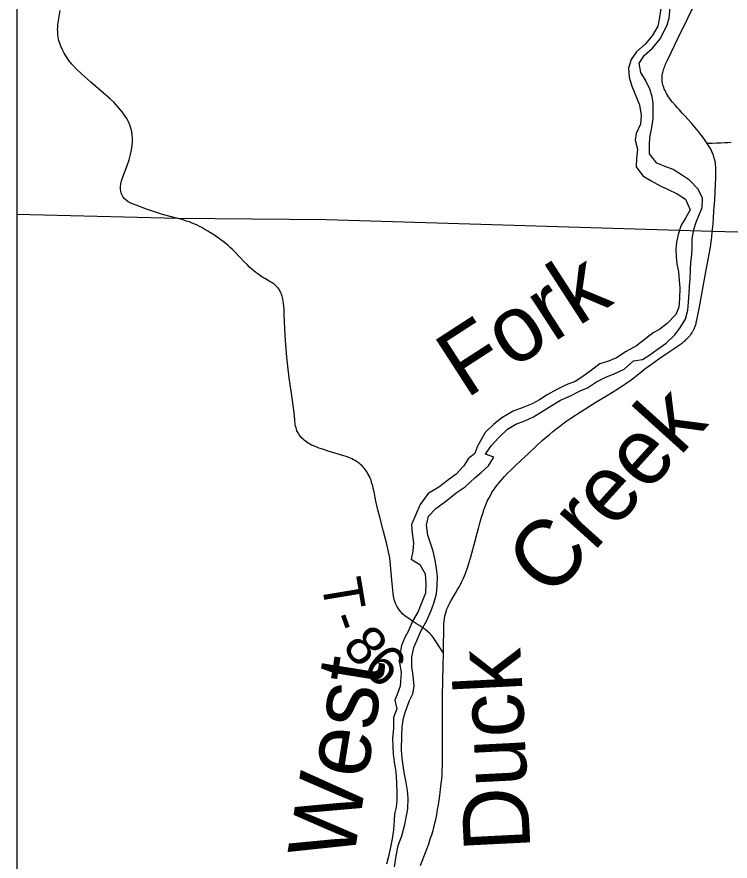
# Model space of a CAD drawing. Extents: x -10.5 to 40.6, y -3.2 to 22.
# Drawn here: x -10.544 to -9.528, y 15.152 to 16.355 of the extents above; entities that cross this region are included whole.
import ezdxf

# ---------------------------------------------------------------- set-up
doc = ezdxf.new("R2010")
doc.units = 0
for name, color, linetype in [('GM_X_Major_River', 7, 'Continuous'), ('GM_X_Major_River_Text', 7, 'Continuous'), ('GM_X_State_Route', 7, 'Continuous'), ('GM_X_Township_Road', 7, 'Continuous'), ('GM_X_Township_Road_Text', 7, 'Continuous'), ('GM_X_Township_Text', 7, 'Continuous'), ('SH_Text', 7, 'Continuous')]:
    doc.layers.add(name, color=color, linetype=linetype)

msp = doc.modelspace()

# ---------------------------------------------------------------- linework, layer by layer
at = {"layer": 'GM_X_Major_River'}
for points in [[(-9.8767, 15.7321), (-9.8682, 15.7436), (-9.8573, 15.7555), (-9.845, 15.7674), (-9.8333, 15.7748), (-9.8205, 15.7795), (-9.8081, 15.7854), (-9.7945, 15.7935), (-9.7829, 15.8009), (-9.7694, 15.809), (-9.7554, 15.8153), (-9.7415, 15.8223), (-9.7309, 15.8266), (-9.7181, 15.8352), (-9.7038, 15.8422), (-9.6933, 15.8465), (-9.679, 15.8531), (-9.6655, 15.8651), (-9.6526, 15.8671), (-9.6421, 15.8734), (-9.6316, 15.8811), (-9.6188, 15.89), (-9.6065, 15.9019), (-9.5994, 15.9115), (-9.5916, 15.9245), (-9.588, 15.9371), (-9.587, 15.9488), (-9.5864, 15.9617), (-9.5858, 15.9716), (-9.5848, 15.9815), (-9.5842, 15.9951), (-9.5836, 16.005), (-9.5826, 16.016), (-9.582, 16.0263), (-9.5821, 16.0388), (-9.5797, 16.0525), (-9.576, 16.0628), (-9.572, 16.0731), (-9.5676, 16.0838), (-9.5674, 16.097), (-9.5733, 16.1098), (-9.5859, 16.1226), (-9.597, 16.1304), (-9.6089, 16.1378), (-9.6203, 16.1422), (-9.6325, 16.147), (-9.6426, 16.1601), (-9.6427, 16.1726), (-9.6421, 16.1836), (-9.6393, 16.1977), (-9.6376, 16.2106), (-9.6373, 16.2205), (-9.6375, 16.2319), (-9.6391, 16.2421), (-9.6423, 16.2523), (-9.6482, 16.2651), (-9.6551, 16.276), (-9.6576, 16.2896), (-9.6498, 16.3011), (-9.6385, 16.3107), (-9.6273, 16.3242), (-9.6181, 16.3429), (-9.6149, 16.3535), (-9.6129, 16.3741)], [(-9.6268, 16.3678), (-9.6285, 16.3545), (-9.631, 16.3423), (-9.6388, 16.3282), (-9.6489, 16.3167), (-9.6612, 16.3055), (-9.6687, 16.2948), (-9.6727, 16.2822), (-9.6717, 16.2693), (-9.6681, 16.2565), (-9.6572, 16.2301), (-9.6547, 16.2153), (-9.6556, 16.2024), (-9.6619, 16.1894), (-9.6633, 16.1799), (-9.6597, 16.1667), (-9.6614, 16.1542), (-9.6616, 16.1416), (-9.652, 16.1289), (-9.6405, 16.1218), (-9.6264, 16.1141), (-9.6169, 16.11), (-9.6035, 16.103), (-9.5913, 16.0956), (-9.5846, 16.0805), (-9.5913, 16.0683), (-9.5976, 16.0587), (-9.6019, 16.045), (-9.6041, 16.0343), (-9.6051, 16.0244), (-9.6049, 16.0135), (-9.6037, 16.0032), (-9.6016, 15.9919), (-9.6003, 15.9794), (-9.5994, 15.9691), (-9.6, 15.954), (-9.6009, 15.9414), (-9.6053, 15.9311), (-9.6177, 15.9181), (-9.6278, 15.91), (-9.6376, 15.9049), (-9.6481, 15.8968), (-9.6612, 15.8864), (-9.6759, 15.8782), (-9.6898, 15.8693), (-9.7011, 15.8646), (-9.7136, 15.8606), (-9.7252, 15.8517), (-9.7376, 15.8425), (-9.7489, 15.8355), (-9.7617, 15.8308), (-9.7749, 15.8241), (-9.7888, 15.8164), (-9.7993, 15.8094), (-9.8098, 15.8036), (-9.8242, 15.7981), (-9.837, 15.7933), (-9.8532, 15.7836), (-9.8648, 15.7747), (-9.8772, 15.7628), (-9.8883, 15.7422), (-9.8915, 15.7327)], [(-9.8915, 15.7327), (-9.9013, 15.7253), (-9.9076, 15.7154), (-9.9181, 15.7035), (-9.9305, 15.6946), (-9.9432, 15.6849), (-9.9583, 15.676), (-9.9698, 15.6603), (-9.9819, 15.6317), (-9.981, 15.6195), (-9.9793, 15.6055), (-9.9799, 15.5938), (-9.9824, 15.582), (-9.9702, 15.5745), (-9.9624, 15.5614), (-9.9614, 15.547), (-9.962, 15.5337), (-9.9671, 15.5207), (-9.9727, 15.5074), (-9.9804, 15.4936), (-9.9863, 15.4802), (-9.9915, 15.4703), (-9.9963, 15.4589), (-9.9984, 15.4456), (-9.999, 15.4346), (-9.9969, 15.4209), (-9.9981, 15.4012), (-10.0018, 15.3909), (-10.0058, 15.381), (-10.003, 15.3689), (-10.0078, 15.3563), (-10.0076, 15.3411), (-10.0089, 15.3267), (-10.0084, 15.3161), (-10.0082, 15.3043), (-10.0065, 15.2929), (-10.0049, 15.2823), (-10.004, 15.2729), (-10.0035, 15.2626), (-10.0029, 15.2494), (-10.0031, 15.238), (-10.0038, 15.2285), (-10.0063, 15.219), (-10.0069, 15.2095), (-10.0075, 15.1962), (-10.0096, 15.1836), (-10.0114, 15.1741), (-10.0142, 15.1604), (-10.0175, 15.1475)], [(-10.006, 15.1435), (-10.004, 15.1591), (-10.0011, 15.1739), (-9.996, 15.1876), (-9.9913, 15.204), (-9.9892, 15.2162), (-9.9874, 15.2261), (-9.9869, 15.2416), (-9.9878, 15.2522), (-9.9898, 15.264), (-9.9923, 15.278), (-9.994, 15.2878), (-9.9952, 15.298), (-9.9961, 15.3102), (-9.9957, 15.3307), (-9.9955, 15.3432), (-9.9933, 15.3553), (-9.9904, 15.3649), (-9.9846, 15.3809), (-9.9802, 15.3904), (-9.9784, 15.4011), (-9.9794, 15.4158), (-9.9814, 15.4287), (-9.9816, 15.4428), (-9.9788, 15.4564), (-9.9725, 15.4706), (-9.9681, 15.4805), (-9.9603, 15.4946), (-9.9541, 15.5088), (-9.9501, 15.5194), (-9.9465, 15.5328), (-9.9455, 15.5449), (-9.9449, 15.5574), (-9.9462, 15.5688), (-9.9482, 15.5809), (-9.9511, 15.5934), (-9.9546, 15.6036), (-9.9586, 15.6164), (-9.9607, 15.6308), (-9.9578, 15.6434), (-9.9473, 15.6545), (-9.9335, 15.6646), (-9.9181, 15.6769), (-9.9053, 15.6854), (-9.8918, 15.6981), (-9.8821, 15.7062), (-9.872, 15.7151), (-9.8646, 15.7277), (-9.8767, 15.7321)]]:
    msp.add_lwpolyline(points, dxfattribs=at)
at = {"layer": 'GM_X_State_Route'}
for points in [[(-9.5532, 16.0492), (-9.5525, 16.056), (-9.5517, 16.0675), (-9.5508, 16.0793), (-9.5502, 16.088), (-9.5497, 16.0955), (-9.5493, 16.1028), (-9.5491, 16.1084), (-9.5488, 16.1135), (-9.5486, 16.1178), (-9.5483, 16.1241), (-9.5482, 16.1303), (-9.5481, 16.1341), (-9.5482, 16.1373), (-9.5483, 16.1417), (-9.5485, 16.1443), (-9.5488, 16.1473), (-9.5493, 16.1499), (-9.5499, 16.1526), (-9.5505, 16.1547), (-9.5509, 16.1561), (-9.5515, 16.1578), (-9.5521, 16.1594), (-9.5526, 16.1608), (-9.5533, 16.1622), (-9.5538, 16.1635), (-9.5545, 16.165), (-9.5552, 16.1664), (-9.5558, 16.1676), (-9.5568, 16.1693), (-9.558, 16.1713), (-9.5603, 16.175), (-9.5633, 16.1794), (-9.5664, 16.1837), (-9.5699, 16.1884), (-9.573, 16.1921), (-9.5781, 16.1982), (-9.583, 16.2039), (-9.588, 16.2095), (-9.592, 16.214), (-9.596, 16.2184), (-9.6001, 16.2228), (-9.6032, 16.2263), (-9.6055, 16.2289), (-9.6097, 16.2338), (-9.6121, 16.2368), (-9.6142, 16.2395), (-9.6157, 16.2415), (-9.6171, 16.2438), (-9.6183, 16.246), (-9.6195, 16.2483), (-9.6206, 16.2505), (-9.6216, 16.2527), (-9.6224, 16.2547), (-9.6232, 16.257), (-9.6238, 16.2591), (-9.6243, 16.2609), (-9.6246, 16.2627), (-9.6248, 16.2648), (-9.6249, 16.2667), (-9.6249, 16.2685), (-9.6247, 16.2704), (-9.6245, 16.2727), (-9.6241, 16.2745), (-9.6238, 16.2762), (-9.6233, 16.2781), (-9.6226, 16.2803), (-9.6219, 16.2825), (-9.6212, 16.2844), (-9.6205, 16.2861), (-9.6198, 16.2878), (-9.6171, 16.2938), (-9.6115, 16.3055), (-9.6021, 16.3245), (-9.5881, 16.3535), (-9.5738, 16.3832)], [(-9.9691, 15.1455), (-9.9657, 15.1541), (-9.9628, 15.1618), (-9.9602, 15.1687), (-9.9574, 15.1765), (-9.9557, 15.1814), (-9.9544, 15.1856), (-9.9531, 15.1894), (-9.9521, 15.1927), (-9.9513, 15.1954), (-9.9506, 15.1982), (-9.9498, 15.2013), (-9.9486, 15.206), (-9.9475, 15.2109), (-9.9461, 15.2177), (-9.9447, 15.2255), (-9.9437, 15.2318), (-9.9422, 15.2416), (-9.9405, 15.254), (-9.9396, 15.2622), (-9.9389, 15.2686), (-9.9384, 15.2747), (-9.9381, 15.2808), (-9.9378, 15.2876), (-9.9378, 15.2939), (-9.9379, 15.2993), (-9.9379, 15.3099), (-9.9378, 15.3255), (-9.9378, 15.336), (-9.9377, 15.3633), (-9.9377, 15.3869), (-9.9367, 15.4311), (-9.9363, 15.4483), (-9.9362, 15.4607), (-9.9361, 15.4793), (-9.9361, 15.4844), (-9.9358, 15.489), (-9.9355, 15.4935), (-9.9349, 15.4977), (-9.9343, 15.501), (-9.9335, 15.5043), (-9.9326, 15.5074), (-9.9315, 15.5107), (-9.9304, 15.5138), (-9.929, 15.517), (-9.9273, 15.5201), (-9.9255, 15.5234), (-9.9194, 15.5336), (-9.9164, 15.5388), (-9.9137, 15.5432), (-9.9122, 15.5462), (-9.9105, 15.5493), (-9.9092, 15.5521), (-9.9079, 15.555), (-9.9065, 15.5584), (-9.9051, 15.5619), (-9.9019, 15.5714), (-9.8976, 15.5857), (-9.8914, 15.6085), (-9.8884, 15.6192), (-9.8865, 15.6258), (-9.8845, 15.6335), (-9.882, 15.6419), (-9.8805, 15.6473), (-9.8789, 15.6524), (-9.8775, 15.6562), (-9.8762, 15.6597), (-9.8752, 15.6622), (-9.8741, 15.6647), (-9.8729, 15.6672), (-9.8715, 15.6697), (-9.8696, 15.673), (-9.8673, 15.6771), (-9.8649, 15.6808), (-9.8628, 15.684), (-9.8604, 15.6873), (-9.8582, 15.6899), (-9.8553, 15.6933), (-9.8526, 15.6965), (-9.8496, 15.6999), (-9.8454, 15.7044), (-9.8404, 15.7092), (-9.8336, 15.7157), (-9.8265, 15.7224), (-9.8151, 15.733), (-9.8045, 15.7432), (-9.7956, 15.7512), (-9.7902, 15.756), (-9.7853, 15.7602), (-9.7808, 15.764), (-9.7762, 15.7677), (-9.7712, 15.7716), (-9.7664, 15.7752), (-9.7606, 15.7795), (-9.7547, 15.7834), (-9.7402, 15.7929), (-9.7191, 15.806), (-9.7017, 15.8167), (-9.6895, 15.8241), (-9.6843, 15.8274), (-9.6797, 15.8304), (-9.6744, 15.834), (-9.6706, 15.8367), (-9.6669, 15.8395), (-9.6579, 15.8465), (-9.6493, 15.8534), (-9.64, 15.8604), (-9.6294, 15.8681), (-9.6192, 15.8748), (-9.6076, 15.8825), (-9.6028, 15.8858), (-9.5983, 15.8888), (-9.597, 15.8898), (-9.5956, 15.8908), (-9.5942, 15.8919), (-9.5925, 15.8933), (-9.5909, 15.8948), (-9.5898, 15.8959), (-9.5888, 15.8969), (-9.5871, 15.8987), (-9.5862, 15.8996), (-9.5854, 15.9007), (-9.5846, 15.9016), (-9.5838, 15.9027), (-9.5824, 15.9047), (-9.5818, 15.9057), (-9.5812, 15.9067), (-9.5806, 15.9077), (-9.58, 15.9087), (-9.5795, 15.9097), (-9.579, 15.9107), (-9.5785, 15.9119), (-9.578, 15.9132), (-9.5775, 15.9144), (-9.5771, 15.9156), (-9.5767, 15.9167), (-9.5764, 15.918), (-9.576, 15.9195), (-9.5753, 15.923), (-9.5715, 15.9418), (-9.5641, 15.9816), (-9.5614, 15.9973), (-9.5591, 16.0094), (-9.5577, 16.0172), (-9.556, 16.0269), (-9.555, 16.0345), (-9.554, 16.0415), (-9.5532, 16.0492)]]:
    msp.add_lwpolyline(points, dxfattribs=at)
at = {"layer": 'GM_X_Township_Road'}
for points in [[(-10.3141, 16.0678), (-10.3149, 16.068), (-10.3367, 16.0738), (-10.3468, 16.0769), (-10.3597, 16.0813), (-10.3743, 16.0868), (-10.3812, 16.0895), (-10.3857, 16.0917), (-10.3887, 16.0939), (-10.3909, 16.096), (-10.3929, 16.0984), (-10.3945, 16.1011), (-10.3957, 16.1039), (-10.3965, 16.1069), (-10.3969, 16.11), (-10.3968, 16.1137), (-10.3962, 16.1174), (-10.3952, 16.1217), (-10.3923, 16.1299), (-10.3878, 16.1421), (-10.3846, 16.1515), (-10.3824, 16.1593), (-10.3809, 16.166), (-10.38, 16.1721), (-10.3796, 16.1771), (-10.3796, 16.182), (-10.38, 16.187), (-10.3808, 16.1919), (-10.382, 16.1967), (-10.3835, 16.2014), (-10.3855, 16.206), (-10.3878, 16.2104), (-10.3901, 16.2141), (-10.3945, 16.2201), (-10.4004, 16.2273), (-10.4059, 16.2332), (-10.4113, 16.2384), (-10.4212, 16.2469), (-10.4391, 16.2623), (-10.452, 16.2739), (-10.4601, 16.2816), (-10.466, 16.288), (-10.4704, 16.2933), (-10.474, 16.2983), (-10.4772, 16.3036), (-10.4797, 16.3086), (-10.4819, 16.3138), (-10.483, 16.3165), (-10.4839, 16.3191), (-10.4846, 16.3215), (-10.4852, 16.3243), (-10.4856, 16.327), (-10.486, 16.33), (-10.4862, 16.3326), (-10.4863, 16.335), (-10.4864, 16.3376), (-10.4863, 16.3405), (-10.486, 16.3439), (-10.4856, 16.3473), (-10.4828, 16.3645)], [(-9.5263, 16.1763), (-9.5305, 16.1759), (-9.5349, 16.1757), (-9.5411, 16.1754), (-9.5467, 16.1752), (-9.5533, 16.175), (-9.5603, 16.175)], [(-9.9715, 15.4879), (-9.9749, 15.4902), (-9.9822, 15.495), (-9.9858, 15.4974), (-9.9909, 15.5009), (-9.9942, 15.5037), (-9.9971, 15.5069), (-10.0005, 15.5113), (-10.0029, 15.515), (-10.0045, 15.5183), (-10.0058, 15.5218), (-10.007, 15.5266), (-10.0081, 15.5334), (-10.0097, 15.5476), (-10.0118, 15.5736), (-10.0131, 15.5841), (-10.0146, 15.5926), (-10.017, 15.6035), (-10.0218, 15.6216), (-10.0278, 15.6438), (-10.03, 15.6528), (-10.0326, 15.665), (-10.0353, 15.6783), (-10.0364, 15.683), (-10.0373, 15.6868), (-10.0383, 15.6899), (-10.0391, 15.6927), (-10.0401, 15.6957), (-10.0411, 15.6979), (-10.042, 15.7001), (-10.0431, 15.7024), (-10.044, 15.7041), (-10.0452, 15.7062), (-10.0466, 15.7082), (-10.0481, 15.7102), (-10.0495, 15.712), (-10.0514, 15.714), (-10.053, 15.7156), (-10.0549, 15.7174), (-10.0568, 15.7189), (-10.0588, 15.7205), (-10.0604, 15.7216), (-10.0624, 15.7229), (-10.0646, 15.7241), (-10.0668, 15.7253), (-10.069, 15.7264), (-10.0713, 15.7273), (-10.075, 15.7286), (-10.0784, 15.7297), (-10.101, 15.7363), (-10.1061, 15.7379), (-10.1105, 15.7394), (-10.1143, 15.7407), (-10.118, 15.7422), (-10.1215, 15.7437), (-10.1243, 15.745), (-10.1268, 15.7463), (-10.1292, 15.7477), (-10.1313, 15.7491), (-10.1333, 15.7504), (-10.1351, 15.7519), (-10.1366, 15.7532), (-10.1392, 15.7559), (-10.1415, 15.7588), (-10.1435, 15.7622), (-10.1452, 15.7653), (-10.1461, 15.7676), (-10.1466, 15.7694), (-10.1472, 15.772), (-10.1477, 15.7743), (-10.1485, 15.781), (-10.1493, 15.7909), (-10.1519, 15.8125), (-10.1533, 15.8217), (-10.1563, 15.8407), (-10.1583, 15.8574), (-10.1596, 15.8704), (-10.1616, 15.8939), (-10.1625, 15.9107), (-10.1633, 15.9311), (-10.1636, 15.9384), (-10.164, 15.9436), (-10.1643, 15.9469), (-10.1648, 15.9503), (-10.1653, 15.9529), (-10.1659, 15.9552), (-10.1665, 15.9573), (-10.1671, 15.9594), (-10.1679, 15.9616), (-10.1688, 15.9634), (-10.1696, 15.9649), (-10.1703, 15.9662), (-10.1715, 15.9681), (-10.1728, 15.9696), (-10.1747, 15.9716), (-10.1764, 15.9731), (-10.1778, 15.9743), (-10.1793, 15.9753), (-10.1808, 15.9763), (-10.1825, 15.9773), (-10.1911, 15.9823), (-10.194, 15.984), (-10.1974, 15.9863), (-10.2011, 15.9889), (-10.2039, 15.9911), (-10.2072, 15.9937), (-10.2096, 15.9959), (-10.2128, 15.9987), (-10.2164, 16.0022), (-10.2205, 16.0064), (-10.2263, 16.0125), (-10.2349, 16.0214), (-10.2378, 16.0243), (-10.2404, 16.0265), (-10.2434, 16.0293), (-10.2464, 16.0318), (-10.2506, 16.0351), (-10.2538, 16.0375), (-10.2591, 16.0412), (-10.2629, 16.044), (-10.2685, 16.0476), (-10.2723, 16.05), (-10.2764, 16.0525), (-10.2809, 16.0551), (-10.2842, 16.0568), (-10.2875, 16.0585), (-10.291, 16.0601), (-10.2944, 16.0614), (-10.2984, 16.063), (-10.3026, 16.0644), (-10.3075, 16.0659), (-10.3133, 16.0675), (-10.3141, 16.0678)], [(-9.9363, 15.4483), (-9.9507, 15.4702), (-9.9533, 15.4737), (-9.9563, 15.4769), (-9.9595, 15.4797), (-9.9646, 15.4833), (-9.9715, 15.4879)]]:
    msp.add_lwpolyline(points, dxfattribs=at)
at = {"layer": 'GM_X_Township_Text'}
msp.add_lwpolyline([(-10.5445, 19.4241), (-10.5445, 16.0741), (-10.3151, 16.0685), (-10.1031, 16.0664), (-9.5534, 16.0497), (-8.7017, 16.0275), (-8.5879, 16.0247), (-8.2615, 16.0223), (-8.2451, 17.3912), (-8.2441, 17.4134)], dxfattribs=at)
at = {"layer": 'SH_Text'}
msp.add_lwpolyline([(-10.5445, 16.0741), (-10.5445, 14.1), (-6.2122, 14.1)], dxfattribs=at)

# ---------------------------------------------------------------- texts
at = {"layer": 'GM_X_Major_River_Text'}
for s, height, rotation, p in [('Fork', 0.0947, 32.9054, (-9.9044, 15.8102)), ('Creek', 0.09471, 47.9058, (-9.7838, 15.524)), ('Duck', 0.09472, 92.8975, (-9.8123, 15.1681)), ('West', 0.09472, 80.9004, (-10.0652, 15.1491))]:
    msp.add_text(s, height=height, rotation=rotation, dxfattribs=at).set_placement(p)
at = {"layer": 'GM_X_Township_Road_Text'}
for s, rotation, p in [('T', 279.4799, (-10.1108, 15.5506)), ('-', 289.652, (-10.1011, 15.4981)), ('8', 310.0312, (-10.0823, 15.4571)), ('6', 317.4219, (-10.0543, 15.4245))]:
    msp.add_text(s, height=0.0568, rotation=rotation, dxfattribs=at).set_placement(p)

doc.saveas('drawing.dxf')
